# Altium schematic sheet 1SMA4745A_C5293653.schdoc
size 127 x 101 mm
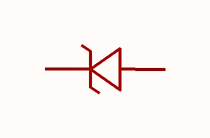
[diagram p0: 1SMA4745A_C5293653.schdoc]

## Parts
D?  1sma4745a_c5293653  [SMAG_L4.3-W2.6-LS5.3-RD]  (value not drawn)

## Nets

Not connected (* = marked no-connect by the designer): D? 1(C) 2(A)

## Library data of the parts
D? = 1sma4745a_c5293653: 二极管配置:1个独立式;稳压值(标称值):16V;稳压值(范围):-;耗散功率(Pd):1W;; Manufacturer: CJ(江苏长电/长晶); AddInBom: yes; ModelId: 3cd8680d946b497db8ea5837610a9736; ModelTransform: 208.661,102.362,0,0,0,0,0,0,0; Diode Configuration: 1个独立式; Zener Voltage(Nom): 16V; Reverse Leakage Current (Ir): 100nA@12.2V; Pd - Power Dissipation: 1W; Impedance(Zzt): 16Ω; Impedance(Zzk): 700Ω; Operating Junction Temperature Range: -55℃~+150℃; Tolerance: ±5%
